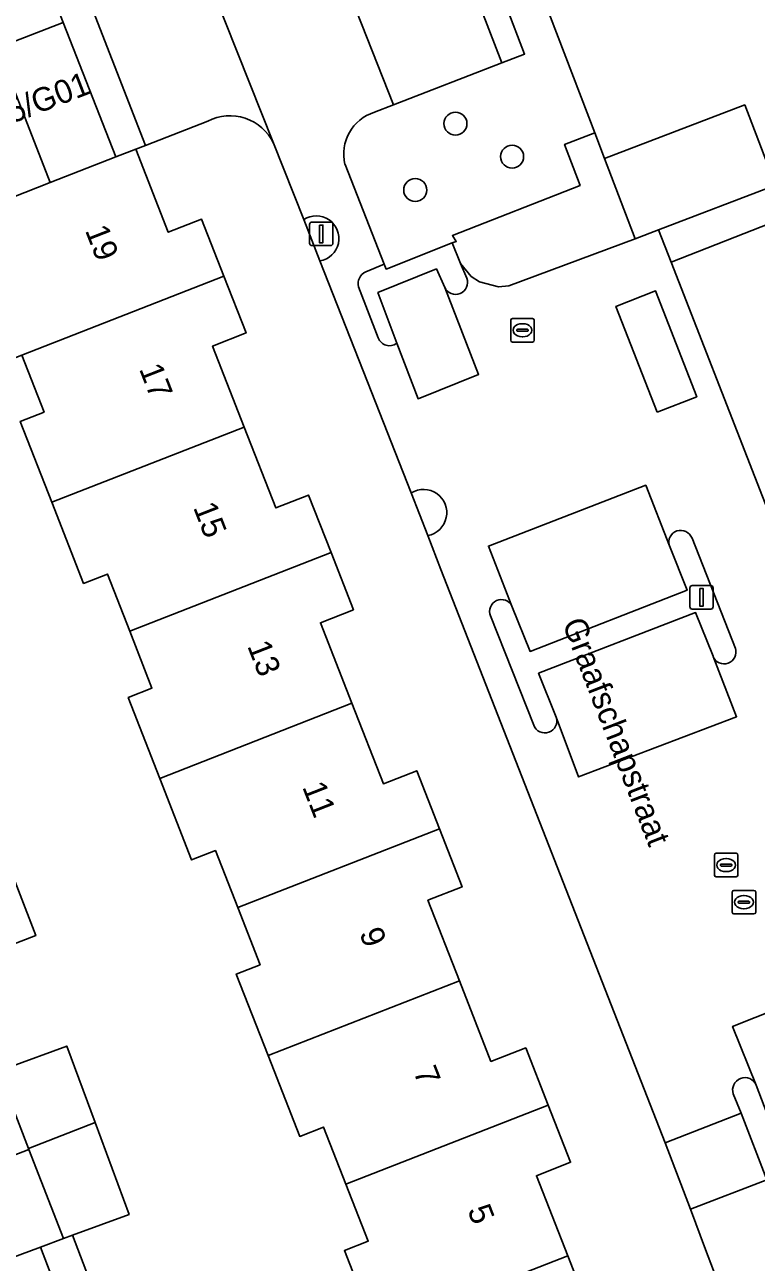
# Model space of a CAD drawing. Extents: x 159680 to 160786, y 387323 to 388340.
# Drawn here: x 160019.8 to 160050.9, y 387799.1 to 387851.7 of the extents above; entities that cross this region are included whole.
import ezdxf

# ---------------------------------------------------------------- set-up
doc = ezdxf.new("R2010")
doc.units = 0
for name, color, linetype in [('IMGEO_Boom', 7, 'Continuous'), ('IMGEO_Erf', 7, 'Continuous'), ('IMGEO_Groenvoorziening', 7, 'Continuous'), ('IMGEO_Hek', 7, 'Continuous'), ('IMGEO_Kolk', 7, 'Continuous'), ('IMGEO_Lichtmast', 7, 'Continuous'), ('IMGEO_Openbare_ruimte_label', 7, 'Continuous'), ('IMGEO_Pand', 7, 'Continuous'), ('IMGEO_Pand_nummerreeks', 7, 'Continuous'), ('IMGEO_Parkeervlak_open', 7, 'Continuous'), ('IMGEO_Rijbaan_lokaal_open', 7, 'Continuous'), ('IMGEO_Rioolput', 7, 'Continuous'), ('IMGEO_Verkeerseiland_open', 7, 'Continuous'), ('IMGEO_Voetpad_open', 7, 'Continuous'), ('IMGEO_Woonerf_open', 7, 'Continuous')]:
    doc.layers.add(name, color=color, linetype=linetype)

msp = doc.modelspace()

# ---------------------------------------------------------------- linework, layer by layer
at = {"layer": 'IMGEO_Boom'}
for centre in [(160038.111, 387847.539), (160040.523, 387846.136), (160036.398, 387844.712)]:
    msp.add_circle(centre, 0.489, dxfattribs=at)
at = {"layer": 'IMGEO_Erf'}
for points in [[(160041.831, 387852.934), (160044.04, 387847.145), (160044.454, 387846.06), (160050.426, 387848.337), (160051.729, 387844.921), (160053.864, 387845.753), (160052.947, 387848.107), (160056.773, 387849.597), (160060.147, 387850.912), (160061.152, 387848.333), (160063.739, 387849.344), (160062.722, 387852.054)], [(160027.57, 387847.646), (160024.913, 387846.614), (160024.501, 387846.454), (160025.884, 387842.919), (160027.305, 387843.474), (160028.252, 387841.052), (160029.199, 387838.632), (160027.774, 387838.075), (160029.121, 387834.632), (160030.467, 387831.191), (160031.859, 387831.736), (160032.814, 387829.295), (160033.768, 387826.855), (160032.361, 387826.305), (160033.701, 387822.88), (160035.041, 387819.455), (160036.461, 387820.01), (160037.427, 387817.54), (160038.394, 387815.069), (160036.938, 387814.499), (160038.279, 387811.07), (160039.621, 387807.639), (160041.106, 387808.22), (160042.058, 387805.785), (160043.011, 387803.35), (160041.559, 387802.782), (160042.894, 387799.368), (160044.229, 387795.955)], [(160037.492, 387828.577), (160036.931, 387830.012), (160036.223, 387831.825), (160034.371, 387836.549), (160032.341, 387841.701), (160031.649, 387843.458), (160030.361, 387846.712)], [(160056.188, 387831.428), (160054.866, 387834.832), (160053.363, 387834.249), (160052.404, 387836.718), (160051.446, 387839.184), (160052.908, 387839.752), (160051.529, 387843.301), (160047.288, 387841.646), (160061.542, 387805.11), (160062.97, 387801.379), (160063.697, 387799.597), (160064.692, 387797.183), (160069.582, 387784.252)], [(160034.718, 387796.174), (160033.38, 387799.594), (160034.397, 387799.991), (160033.446, 387802.421), (160032.495, 387804.851), (160031.479, 387804.454), (160030.136, 387807.888), (160028.779, 387811.356), (160029.795, 387811.753), (160028.843, 387814.187), (160027.894, 387816.611), (160026.879, 387816.214), (160025.522, 387819.685), (160024.177, 387823.123), (160025.191, 387823.519), (160024.242, 387825.946), (160023.291, 387828.375), (160022.278, 387827.979), (160020.927, 387831.432), (160019.582, 387834.87), (160020.595, 387835.266), (160019.646, 387837.691)], [(160052.63, 387789.479), (160048.749, 387799.635), (160048.124, 387801.362), (160047.035, 387804.174), (160037.492, 387828.577)], [(160018.69, 387817.016), (160020.244, 387812.999), (160017.369, 387811.887)], [(160019.087, 387807.381), (160021.565, 387808.297), (160022.769, 387805.041), (160024.214, 387801.135), (160021.808, 387800.245), (160029.428, 387780.26)], [(160018.878, 387776.295), (160025.281, 387778.75), (160022.561, 387785.844), (160025.355, 387786.915), (160025.019, 387787.793), (160022.661, 387786.88), (160021.157, 387790.765), (160019.877, 387794.073), (160022.259, 387794.994), (160020.44, 387799.739), (160018.804, 387799.133)]]:
    msp.add_lwpolyline(points, dxfattribs=at)
msp.add_arc((160028.508, 387845.811), 2.061, 25.9319, 117.0628, dxfattribs=at)
at = {"layer": 'IMGEO_Groenvoorziening'}
msp.add_lwpolyline([(160033.408, 387845.806), (160035.072, 387841.564), (160035.154, 387841.354), (160037.974, 387842.462), (160038.142, 387842.528), (160037.984, 387842.779), (160043.418, 387844.911), (160042.754, 387846.655), (160044.04, 387847.145), (160041.831, 387852.934), (160041.694, 387852.881), (160041.624, 387853.061), (160040.271, 387852.536), (160041.055, 387850.499), (160040.087, 387850.124), (160035.468, 387848.337), (160034.659, 387848.024)], dxfattribs=at)
msp.add_arc((160035.213, 387846.25), 1.859, 107.3346, 193.8175, dxfattribs=at)
at = {"layer": 'IMGEO_Hek'}
msp.add_lwpolyline([(160044.04, 387847.145), (160041.831, 387852.934)], dxfattribs=at)
at = {"layer": 'IMGEO_Kolk'}
for p, q in [((160040.463, 387838.321), (160040.463, 387839.173)), ((160040.538, 387839.247), (160041.39, 387839.247)), ((160041.464, 387839.173), (160041.464, 387838.321)), ((160040.722, 387838.741), (160040.722, 387838.753)), ((160041.16, 387838.704), (160040.762, 387838.704)), ((160040.765, 387838.79), (160041.163, 387838.79)), ((160040.951, 387839.027), (160040.976, 387839.027)), ((160041.206, 387838.753), (160041.206, 387838.741)), ((160041.39, 387838.247), (160040.538, 387838.247)), ((160040.974, 387838.467), (160040.949, 387838.467)), ((160049.892, 387813.989), (160049.892, 387814.841)), ((160049.967, 387814.915), (160050.819, 387814.915)), ((160050.194, 387814.458), (160050.592, 387814.458)), ((160050.38, 387814.695), (160050.405, 387814.695)), ((160050.893, 387814.841), (160050.893, 387813.989)), ((160050.819, 387813.915), (160049.967, 387813.915)), ((160050.151, 387814.409), (160050.151, 387814.421)), ((160050.589, 387814.372), (160050.191, 387814.372)), ((160050.403, 387814.135), (160050.378, 387814.135)), ((160050.635, 387814.421), (160050.635, 387814.409))]:
    msp.add_line(p, q, dxfattribs=at)
for points in [[(160040.463, 387838.321), (160040.463, 387839.173)], [(160040.538, 387839.247), (160041.39, 387839.247)], [(160041.464, 387839.173), (160041.464, 387838.321)], [(160041.39, 387838.247), (160040.538, 387838.247)], [(160049.892, 387813.989), (160049.892, 387814.841)], [(160049.967, 387814.915), (160050.819, 387814.915)], [(160050.893, 387814.841), (160050.893, 387813.989)], [(160050.819, 387813.915), (160049.967, 387813.915)]]:
    msp.add_lwpolyline(points, dxfattribs=at)
for centre, radius, start, end in [((160040.54, 387839.171), 0.0765, 91.552, 178.448), ((160040.54, 387839.171), 0.0765, 91.552, 178.448), ((160041.388, 387839.171), 0.0765, 1.552, 88.448), ((160041.388, 387839.171), 0.0765, 1.552, 88.448), ((160040.762, 387838.75), 0.0403, 85.8775, 175.7526), ((160040.759, 387838.74), 0.0366, 178.938, 274.7102), ((160041.163, 387838.747), 0.043, 264.8664, 352.4533), ((160041.167, 387838.752), 0.0386, 1.7309, 96.639), ((160040.54, 387838.323), 0.0765, 181.552, 268.448), ((160040.54, 387838.323), 0.0765, 181.552, 268.448), ((160041.388, 387838.323), 0.0765, 271.552, 358.448), ((160041.388, 387838.323), 0.0765, 271.552, 358.448), ((160049.969, 387814.839), 0.0765, 91.552, 178.448), ((160049.969, 387814.839), 0.0765, 91.552, 178.448), ((160050.191, 387814.418), 0.0403, 85.8775, 175.7526), ((160050.596, 387814.42), 0.0386, 1.7309, 96.639), ((160050.817, 387814.839), 0.0765, 1.552, 88.448), ((160050.817, 387814.839), 0.0765, 1.552, 88.448), ((160049.969, 387813.991), 0.0765, 181.552, 268.448), ((160049.969, 387813.991), 0.0765, 181.552, 268.448), ((160050.188, 387814.408), 0.0366, 178.938, 274.7102), ((160050.592, 387814.415), 0.043, 264.8664, 352.4533), ((160050.817, 387813.991), 0.0765, 271.552, 358.448), ((160050.817, 387813.991), 0.0765, 271.552, 358.448)]:
    msp.add_arc(centre, radius, start, end, dxfattribs=at)
for centre, major_axis, ratio, start_param, end_param in [((160040.95, 387838.747), (-0.387, 0.002), 0.722429, 4.712389, 7.853982), ((160040.975, 387838.747), (-0.39, 0.002), 0.717154, 1.570796, 4.712389), ((160050.379, 387814.415), (-0.387, 0.002), 0.722429, 4.712389, 7.853982), ((160050.404, 387814.415), (-0.39, 0.002), 0.717154, 1.570796, 4.712389)]:
    msp.add_ellipse(centre, major_axis=major_axis, ratio=ratio, start_param=start_param, end_param=end_param, dxfattribs=at)
at = {"layer": 'IMGEO_Lichtmast'}
for p, q in [((160031.901, 387842.448), (160031.901, 387843.248)), ((160031.901, 387843.248), (160031.901, 387842.448)), ((160032.001, 387843.348), (160032.791, 387843.348)), ((160032.791, 387843.348), (160032.001, 387843.348)), ((160032.891, 387843.248), (160032.891, 387842.448)), ((160032.891, 387842.448), (160032.891, 387843.248)), ((160032.791, 387842.348), (160032.001, 387842.348)), ((160032.001, 387842.348), (160032.791, 387842.348)), ((160048.09, 387826.986), (160048.09, 387827.786)), ((160048.09, 387827.786), (160048.09, 387826.986)), ((160048.19, 387827.886), (160048.98, 387827.886)), ((160048.98, 387827.886), (160048.19, 387827.886)), ((160049.08, 387827.786), (160049.08, 387826.986)), ((160049.08, 387826.986), (160049.08, 387827.786)), ((160048.98, 387826.886), (160048.19, 387826.886)), ((160048.19, 387826.886), (160048.98, 387826.886))]:
    msp.add_line(p, q, dxfattribs=at)
for points in [[(160032.321, 387843.223), (160032.471, 387843.223), (160032.471, 387842.473), (160032.321, 387842.473), (160032.321, 387843.223)], [(160048.51, 387827.761), (160048.66, 387827.761), (160048.66, 387827.011), (160048.51, 387827.011), (160048.51, 387827.761)]]:
    msp.add_lwpolyline(points, dxfattribs=at)
for centre, start, end in [((160032.001, 387843.248), 90, 180), ((160032.001, 387843.248), 90, 180), ((160032.791, 387843.248), 0, 90), ((160032.791, 387843.248), 360, 90), ((160032.001, 387842.448), 180, 270), ((160032.001, 387842.448), 180, 270), ((160032.791, 387842.448), 270, 0), ((160032.791, 387842.448), 270, 0), ((160048.19, 387827.786), 90, 180), ((160048.19, 387827.786), 90, 180), ((160048.98, 387827.786), 0, 90), ((160048.98, 387827.786), 360, 90), ((160048.19, 387826.986), 180, 270), ((160048.19, 387826.986), 180, 270), ((160048.98, 387826.986), 270, 0), ((160048.98, 387826.986), 270, 0)]:
    msp.add_arc(centre, 0.1, start, end, dxfattribs=at)
at = {"layer": 'IMGEO_Pand'}
for points in [[(160018.616, 387850.757), (160020.857, 387845.031), (160023.646, 387846.12), (160021.405, 387851.848)], [(160015.828, 387849.666), (160018.068, 387843.941), (160020.857, 387845.031), (160018.616, 387850.757)], [(160046.751, 387843.023), (160051.729, 387844.921), (160050.426, 387848.337), (160044.454, 387846.06), (160045.757, 387842.644)], [(160024.501, 387846.454), (160023.646, 387846.12), (160020.857, 387845.031), (160018.068, 387843.941), (160016.303, 387843.252), (160018.633, 387837.295), (160019.646, 387837.691), (160028.252, 387841.052), (160027.305, 387843.474), (160025.884, 387842.919)], [(160028.252, 387841.052), (160019.646, 387837.691), (160020.595, 387835.266), (160019.582, 387834.87), (160020.927, 387831.432), (160029.121, 387834.632), (160027.774, 387838.075), (160029.199, 387838.632)], [(160029.121, 387834.632), (160020.927, 387831.432), (160022.278, 387827.979), (160023.291, 387828.375), (160024.242, 387825.946), (160032.814, 387829.295), (160031.859, 387831.736), (160030.467, 387831.191)], [(160032.814, 387829.295), (160024.242, 387825.946), (160025.191, 387823.519), (160024.177, 387823.123), (160025.522, 387819.685), (160033.701, 387822.88), (160032.361, 387826.305), (160033.768, 387826.855)], [(160033.701, 387822.88), (160025.522, 387819.685), (160026.879, 387816.214), (160027.894, 387816.611), (160028.843, 387814.187), (160037.427, 387817.54), (160036.461, 387820.01), (160035.041, 387819.455)], [(160037.427, 387817.54), (160028.843, 387814.187), (160029.795, 387811.753), (160028.779, 387811.356), (160030.136, 387807.888), (160038.279, 387811.07), (160036.938, 387814.499), (160038.394, 387815.069)], [(160018.69, 387817.016), (160015.818, 387815.894), (160017.369, 387811.887), (160020.244, 387812.999)], [(160038.279, 387811.07), (160030.136, 387807.888), (160031.479, 387804.454), (160032.495, 387804.851), (160033.446, 387802.421), (160042.058, 387805.785), (160041.106, 387808.22), (160039.621, 387807.639)], [(160021.565, 387808.297), (160019.087, 387807.381), (160018.658, 387807.222), (160019.939, 387803.934), (160022.769, 387805.041)], [(160018.658, 387807.222), (160017.707, 387806.87), (160016.155, 387806.296), (160017.407, 387802.911), (160019.952, 387803.9), (160019.939, 387803.934)], [(160042.058, 387805.785), (160033.446, 387802.421), (160034.397, 387799.991), (160033.38, 387799.594), (160034.718, 387796.174), (160042.894, 387799.368), (160041.559, 387802.782), (160043.011, 387803.35)], [(160022.769, 387805.041), (160019.939, 387803.934), (160019.952, 387803.9), (160021.43, 387800.105), (160021.808, 387800.245), (160024.214, 387801.135)], [(160019.952, 387803.9), (160017.407, 387802.911), (160018.804, 387799.133), (160020.44, 387799.739), (160021.43, 387800.105)], [(160042.894, 387799.368), (160034.718, 387796.174), (160036.06, 387792.745), (160037.076, 387793.143), (160038.027, 387790.713), (160046.626, 387794.072), (160045.669, 387796.518), (160044.229, 387795.955)]]:
    msp.add_lwpolyline(points, close=True, dxfattribs=at)
at = {"layer": 'IMGEO_Parkeervlak_open'}
for points in [[(160040.087, 387850.124), (160034.966, 387863.392), (160030.234, 387861.596), (160035.468, 387848.337)], [(160007.462, 387846.394), (160010.251, 387847.485), (160013.04, 387848.576), (160015.828, 387849.666), (160018.616, 387850.757), (160021.405, 387851.848), (160019.276, 387857.317), (160000, 387849.829), (159984.066, 387843.64), (159986.193, 387838.174), (159989.023, 387839.275), (159991.853, 387840.376), (159994.684, 387841.478), (159997.514, 387842.579), (160000.344, 387843.68), (160003.174, 387844.781), (160004.383, 387845.202), (160004.674, 387845.303)], [(160037.652, 387840.574), (160037.303, 387841.359), (160034.811, 387840.349), (160035.608, 387838.196), (160036.521, 387835.831), (160039.093, 387836.868)], [(160046.699, 387835.264), (160048.385, 387835.921), (160046.63, 387840.421), (160044.944, 387839.764)], [(160040.517, 387827.009), (160041.287, 387825.086), (160047.972, 387827.686), (160047.217, 387829.578), (160046.209, 387832.157), (160039.511, 387829.565)], [(160049.075, 387824.879), (160048.33, 387826.74), (160041.649, 387824.153), (160042.397, 387822.284), (160043.353, 387819.744), (160050.082, 387822.305), (160049.079, 387824.869)], [(160050.917, 387806.63), (160051.638, 387804.733), (160058.336, 387807.328), (160057.605, 387809.183), (160056.595, 387811.779), (160049.909, 387809.132)]]:
    msp.add_lwpolyline(points, close=True, dxfattribs=at)
msp.add_lwpolyline([(160030.361, 387846.712), (160025.23, 387859.629), (160020.554, 387857.813), (160024.913, 387846.614), (160027.57, 387847.646)], dxfattribs=at)
msp.add_arc((160028.508, 387845.811), 2.061, 25.9319, 117.0628, dxfattribs=at)
at = {"layer": 'IMGEO_Rijbaan_lokaal_open'}
msp.add_lwpolyline([(160050.275, 387805.446), (160047.035, 387804.174), (160048.124, 387801.362), (160051.362, 387802.608)], close=True, dxfattribs=at)
at = {"layer": 'IMGEO_Rioolput'}
for p, q in [((160049.133, 387815.57), (160049.133, 387816.422)), ((160049.208, 387816.496), (160050.06, 387816.496)), ((160049.392, 387815.99), (160049.392, 387816.002)), ((160049.435, 387816.039), (160049.833, 387816.039)), ((160049.621, 387816.276), (160049.646, 387816.276)), ((160049.876, 387816.002), (160049.876, 387815.99)), ((160050.134, 387816.422), (160050.134, 387815.57)), ((160050.06, 387815.496), (160049.208, 387815.496)), ((160049.83, 387815.953), (160049.432, 387815.953)), ((160049.644, 387815.716), (160049.619, 387815.716))]:
    msp.add_line(p, q, dxfattribs=at)
for points in [[(160049.133, 387815.57), (160049.133, 387816.422)], [(160049.208, 387816.496), (160050.06, 387816.496)], [(160050.134, 387816.422), (160050.134, 387815.57)], [(160050.06, 387815.496), (160049.208, 387815.496)]]:
    msp.add_lwpolyline(points, dxfattribs=at)
for centre, radius, start, end in [((160049.21, 387816.42), 0.0765, 91.552, 178.448), ((160049.21, 387816.42), 0.0765, 91.552, 178.448), ((160049.432, 387815.999), 0.0403, 85.8775, 175.7526), ((160049.837, 387816.001), 0.0386, 1.7309, 96.639), ((160050.058, 387816.42), 0.0765, 1.552, 88.448), ((160050.058, 387816.42), 0.0765, 1.552, 88.448), ((160049.21, 387815.572), 0.0765, 181.552, 268.448), ((160049.21, 387815.572), 0.0765, 181.552, 268.448), ((160049.429, 387815.989), 0.0366, 178.938, 274.7102), ((160049.833, 387815.996), 0.043, 264.8664, 352.4533), ((160050.058, 387815.572), 0.0765, 271.552, 358.448), ((160050.058, 387815.572), 0.0765, 271.552, 358.448)]:
    msp.add_arc(centre, radius, start, end, dxfattribs=at)
for centre, major_axis, ratio, start_param, end_param in [((160049.62, 387815.996), (-0.387, 0.002), 0.722429, 4.712389, 7.853982), ((160049.645, 387815.996), (-0.39, 0.002), 0.717154, 1.570796, 4.712389)]:
    msp.add_ellipse(centre, major_axis=major_axis, ratio=ratio, start_param=start_param, end_param=end_param, dxfattribs=at)
at = {"layer": 'IMGEO_Verkeerseiland_open'}
for points in [[(160031.649, 387843.458), (160032.341, 387841.701)], [(160038.591, 387840.965), (160038.332, 387841.594), (160037.974, 387842.462), (160035.154, 387841.354), (160035.072, 387841.564), (160034.295, 387841.232)], [(160035.608, 387838.196), (160034.811, 387840.349), (160037.303, 387841.359), (160037.652, 387840.574)], [(160033.987, 387840.592), (160034.826, 387838.423)], [(160036.223, 387831.825), (160036.931, 387830.012)], [(160050.026, 387825.216), (160048.182, 387829.903)], [(160047.217, 387829.578), (160047.972, 387827.686), (160041.287, 387825.086), (160040.517, 387827.009)], [(160039.602, 387826.593), (160041.446, 387821.946)], [(160042.397, 387822.284), (160041.649, 387824.153), (160048.33, 387826.74), (160049.075, 387824.879), (160049.079, 387824.869)], [(160057.605, 387809.183), (160058.336, 387807.328), (160051.638, 387804.733), (160050.917, 387806.63)], [(160049.94, 387806.257), (160050.275, 387805.446), (160051.362, 387802.608), (160051.759, 387801.571)]]:
    msp.add_lwpolyline(points, dxfattribs=at)
for centre, radius, start, end in [((160032.182, 387842.653), 0.965, 279.4868, 123.5075), ((160034.499, 387840.74), 0.533, 112.527, 196.0746), ((160038.117, 387840.78), 0.509, 203.8331, 21.3807), ((160035.3, 387838.595), 0.504, 199.958, 307.668), ((160036.753, 387830.987), 0.991, 280.36, 122.3025), ((160047.704, 387829.726), 0.509, 20.3102, 196.9155), ((160040.065, 387826.788), 0.503, 26.0268, 202.8705), ((160049.547, 387825.058), 0.505, 201.9479, 18.2998), ((160041.919, 387822.123), 0.505, 200.5792, 18.5528), ((160050.434, 387806.429), 0.523, 22.5478, 199.244)]:
    msp.add_arc(centre, radius, start, end, dxfattribs=at)
at = {"layer": 'IMGEO_Voetpad_open'}
for points in [[(160085.896, 387883.295), (160091.41, 387885.467), (160090.509, 387887.754), (160089.681, 387887.432), (160089.502, 387887.898), (160059.275, 387876.138), (160029.506, 387864.544), (160029.686, 387864.078), (160024.281, 387861.973), (160025.23, 387859.629), (160030.234, 387861.596), (160034.966, 387863.392), (160040.087, 387850.124), (160041.055, 387850.499), (160040.271, 387852.536), (160035.948, 387863.765)], [(160038.786, 387841.038), (160039.141, 387840.807), (160039.942, 387840.6), (160040.387, 387840.641), (160045.757, 387842.644), (160044.454, 387846.06), (160044.04, 387847.145), (160042.754, 387846.655), (160043.418, 387844.911), (160037.984, 387842.779), (160038.142, 387842.528), (160037.974, 387842.462), (160038.332, 387841.594)]]:
    msp.add_lwpolyline(points, close=True, dxfattribs=at)
for points in [[(159985.192, 387831.126), (159987.782, 387832.114), (159988.449, 387832.375), (159986.193, 387838.174), (159984.066, 387843.64), (160000, 387849.829), (160019.276, 387857.317), (160021.405, 387851.848), (160023.646, 387846.12), (160024.501, 387846.454), (160024.913, 387846.614), (160020.554, 387857.813), (160025.23, 387859.629), (160024.281, 387861.973), (160023.396, 387861.628), (160023.216, 387862.094), (160018.212, 387860.145), (160018.599, 387859.148), (159983.304, 387845.437), (159982.917, 387846.434), (159980.753, 387845.594)], [(160073.545, 387852.869), (160069.523, 387851.36), (160063.789, 387849.21), (160063.739, 387849.344), (160061.152, 387848.333), (160061.204, 387848.2), (160057.826, 387846.884), (160054.004, 387845.395), (160053.864, 387845.753), (160051.729, 387844.921), (160046.751, 387843.023), (160047.288, 387841.646), (160051.529, 387843.301), (160056.19, 387845.112), (160059.746, 387846.493), (160066.211, 387848.846), (160066.302, 387848.619), (160069.229, 387849.896), (160071.704, 387844.223), (160072.45, 387842.516), (160072.775, 387841.675), (160072.932, 387841.736), (160074.21, 387838.436), (160075.716, 387834.544)], [(160029.428, 387780.26), (160021.808, 387800.245), (160021.43, 387800.105), (160020.44, 387799.739), (160022.259, 387794.994)]]:
    msp.add_lwpolyline(points, dxfattribs=at)
at = {"layer": 'IMGEO_Woonerf_open'}
for points in [[(160034.659, 387848.024), (160035.468, 387848.337), (160030.234, 387861.596), (160025.23, 387859.629), (160030.361, 387846.712), (160031.649, 387843.458)], [(160034.295, 387841.232), (160035.072, 387841.564), (160033.408, 387845.806)], [(160047.288, 387841.646), (160046.751, 387843.023), (160045.757, 387842.644), (160040.387, 387840.641), (160039.942, 387840.6), (160039.141, 387840.807), (160038.786, 387841.038), (160038.332, 387841.594), (160038.591, 387840.965)], [(160032.341, 387841.701), (160034.371, 387836.549), (160036.223, 387831.825)], [(160062.82, 387801.331), (160062.97, 387801.379), (160061.542, 387805.11), (160047.288, 387841.646)], [(160034.826, 387838.423), (160033.987, 387840.592)], [(160037.652, 387840.574), (160039.093, 387836.868), (160036.521, 387835.831), (160035.608, 387838.196)], [(160040.517, 387827.009), (160039.511, 387829.565), (160046.209, 387832.157), (160047.217, 387829.578)], [(160036.931, 387830.012), (160037.492, 387828.577), (160047.035, 387804.174), (160050.275, 387805.446), (160049.94, 387806.257)], [(160048.182, 387829.903), (160050.026, 387825.216)], [(160041.446, 387821.946), (160039.602, 387826.593)], [(160049.079, 387824.869), (160050.082, 387822.305), (160043.353, 387819.744)], [(160043.353, 387819.744), (160042.397, 387822.284)], [(160050.917, 387806.63), (160049.909, 387809.132), (160056.595, 387811.779), (160057.605, 387809.183)], [(160051.759, 387801.571), (160051.362, 387802.608), (160048.124, 387801.362), (160048.749, 387799.635), (160052.63, 387789.479), (160053.15, 387788.119), (160054.983, 387788.763), (160056.534, 387789.34), (160055.952, 387790.852)]]:
    msp.add_lwpolyline(points, dxfattribs=at)
msp.add_lwpolyline([(160046.699, 387835.264), (160044.944, 387839.764), (160046.63, 387840.421), (160048.385, 387835.921)], close=True, dxfattribs=at)
for centre, radius, start, end in [((160035.213, 387846.25), 1.859, 107.3346, 193.8175), ((160032.182, 387842.653), 0.965, 279.4868, 123.5075), ((160034.499, 387840.74), 0.533, 112.527, 196.0746), ((160038.117, 387840.78), 0.509, 203.8331, 21.3807), ((160035.3, 387838.595), 0.504, 199.958, 307.668), ((160036.753, 387830.987), 0.991, 280.36, 122.3025), ((160047.704, 387829.726), 0.509, 20.3102, 196.9155), ((160040.065, 387826.788), 0.503, 26.0268, 202.8705), ((160049.547, 387825.058), 0.505, 201.9479, 18.2998), ((160041.919, 387822.123), 0.505, 200.5792, 18.5528), ((160050.434, 387806.429), 0.523, 22.5478, 199.244)]:
    msp.add_arc(centre, radius, start, end, dxfattribs=at)

# ---------------------------------------------------------------- texts
at = {"layer": 'IMGEO_Openbare_ruimte_label'}
msp.add_text('Graafschapstraat', height=1, rotation=291.2268, dxfattribs=at).set_placement((160042.645, 387826.284))
at = {"layer": 'IMGEO_Pand_nummerreeks'}
for s, rotation, p in [('15/G01', 21.0733, (160018.547, 387847.269)), ('19', 291.3367, (160022.33, 387842.999)), ('17', 291.3367, (160024.631, 387837.107)), ('15', 291.3367, (160026.933, 387831.214)), ('13', 291.3367, (160029.235, 387825.321)), ('11', 291.3367, (160031.577, 387819.321)), ('9', 291.3367, (160034.005, 387813.107)), ('7', 291.3367, (160036.307, 387807.214)), ('5', 291.3367, (160038.608, 387801.321))]:
    msp.add_text(s, height=1, rotation=rotation, dxfattribs=at).set_placement(p)

doc.saveas('drawing.dxf')
